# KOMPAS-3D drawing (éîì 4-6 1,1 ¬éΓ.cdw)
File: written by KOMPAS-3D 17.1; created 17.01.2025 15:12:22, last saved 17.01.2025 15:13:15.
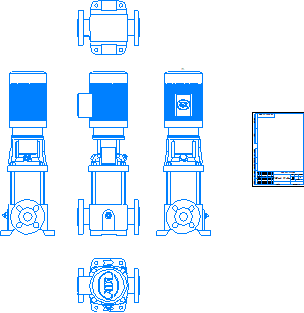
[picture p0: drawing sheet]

Sheet 1: A4, portrait

Title block, sheet 1: name: ВМН 4-6 1,1 кВт; designation: ВМН 4-6 1,1 кВт; sheets: 1; sheet format: A4; stored path: \\adlc.lan\data\АДЛ_ПКД\3D-модели\ADL production\Насосы ГРАНПАМП\Насосы ВМН\ВМН4\KOMPAS 2D\ВМН 4-6 1,1 кВт.cdw

Views: Вид 1, Спереди, Проекционный вид 2, Проекционный вид 3, Проекционный вид 4, Проекционный вид 5
Referenced files in \\adlc.lan\data\АДЛ_ПКД\3D-модели\ADL production\Насосы ГРАНПАМП\Насосы ВМН\ВМН4\KOMPAS 3D\: ВМН 4-6 1,1 кВт.m3d
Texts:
  Andrey
  АДЛ
Dimensions and other numbers on the sheet: 1:1; 1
